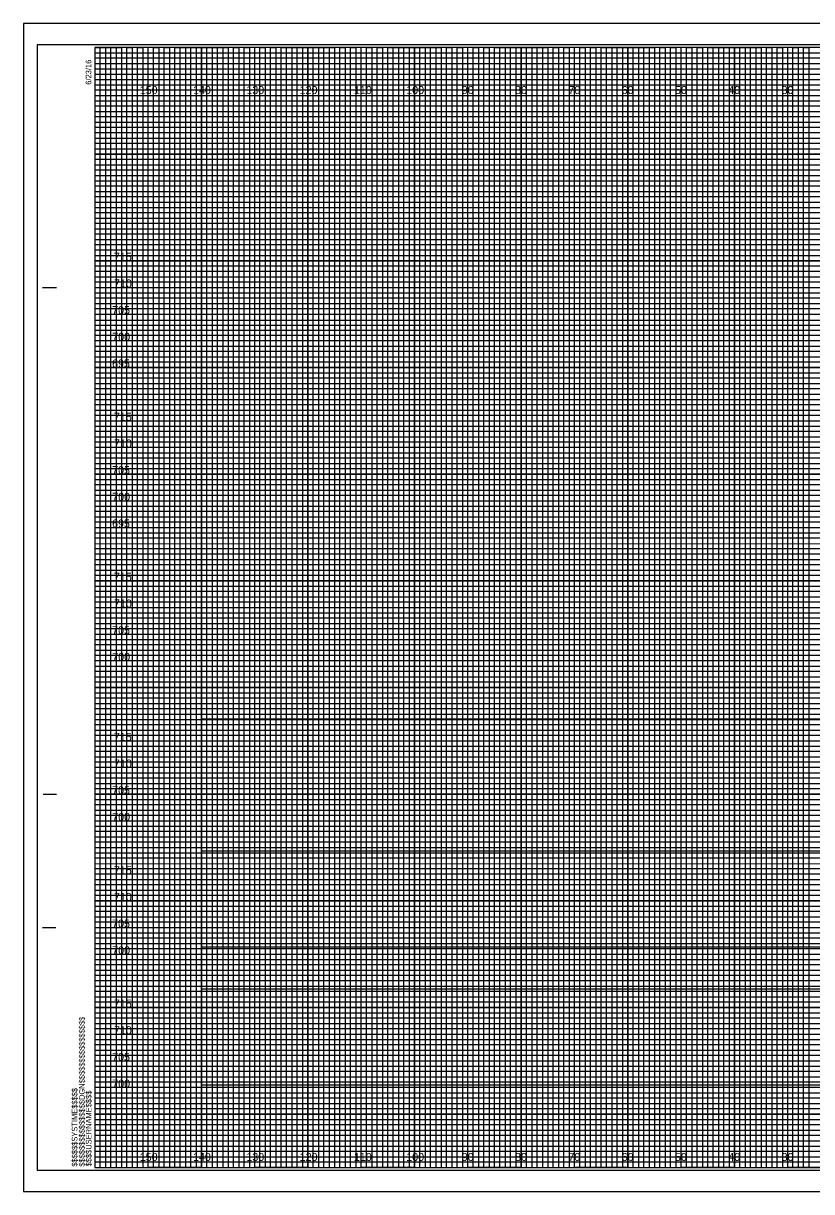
# Model space of a CAD drawing. Extents: x -13 to 323, y -5 to 215.
# Drawn here: x -13.4 to 134.5, y -4.5 to 214.5 of the extents above; entities that cross this region are included whole.
import ezdxf

# ---------------------------------------------------------------- set-up
doc = ezdxf.new("R2010")
doc.units = 0
for name, color, linetype in [('Prop XS Elevation Labels', 7, 'Continuous'), ('Prop XS Offset Labels', 7, 'Continuous'), ('Scratch_Level_3', 7, 'Continuous'), ('Sheet Cross Section CELL', 7, 'Continuous'), ('Sheet Cross Section Grid Major CELL', 7, 'Continuous'), ('Sheet Cross Section Grid Middle CELL', 7, 'Continuous'), ('Sheet Cross Section Grid Minor 1 CELL', 7, 'Continuous'), ('Sheet Cross Section Grid Minor 2 CELL', 7, 'Continuous'), ('Sheet Cutting Line CELL', 7, 'Continuous'), ('Sheet DOT Grid CELL', 7, 'Continuous'), ('Sheet Plot Border Inside CELL', 7, 'Continuous'), ('Sheet Plot Border Outside CELL', 7, 'Continuous')]:
    doc.layers.add(name, color=color, linetype=linetype)

msp = doc.modelspace()

# ---------------------------------------------------------------- linework, layer by layer
at = {"layer": 'Scratch_Level_3'}
for points in [[(20, 84.12), (300, 84.12), (300, 66.04), (20, 66.04)], [(20, 59.39), (300, 59.39), (300, 41.31), (20, 41.31)], [(20, 33.54), (300, 33.54), (300, 15.46), (20, 15.46)]]:
    msp.add_lwpolyline(points, close=True, dxfattribs=at)
at = {"layer": 'Sheet Cross Section CELL'}
for p, q in [((-9.8, 165), (-7.3, 165)), ((-9.7, 165), (-7.2, 165)), ((-9.7, 70), (-7.2, 70)), ((-9.8, 45), (-7.3, 45)), ((0, 0), (0, 0)), ((0, 0), (0, 0)), ((0, 0), (0, 0)), ((0, 0), (0, 0)), ((0, 0), (0, 0)), ((0, 0), (0, 0)), ((0, 0), (0, 0))]:
    msp.add_line(p, q, dxfattribs=at)
msp.add_lwpolyline([(320, 210), (0, 210), (0, 0), (320, 0)], close=True, dxfattribs=at)
at = {"layer": 'Sheet Cross Section Grid Major CELL'}
for p, q in [((10, 210), (0, 210)), ((10, 0), (10, 210)), ((30, 210), (20, 210)), ((20, 210), (20, 0)), ((30, 0), (30, 210)), ((50, 210), (40, 210)), ((40, 210), (40, 0)), ((50, 0), (50, 210)), ((70, 210), (60, 210)), ((60, 210), (60, 0)), ((70, 0), (70, 210)), ((90, 210), (80, 210)), ((80, 210), (80, 0)), ((90, 0), (90, 210)), ((110, 210), (100, 210)), ((100, 210), (100, 0)), ((110, 0), (110, 210)), ((130, 210), (120, 210)), ((120, 210), (120, 0)), ((130, 0), (130, 210)), ((20, 0), (10, 0)), ((40, 0), (30, 0)), ((60, 0), (50, 0)), ((80, 0), (70, 0)), ((100, 0), (90, 0)), ((120, 0), (110, 0)), ((140, 0), (130, 0))]:
    msp.add_line(p, q, dxfattribs=at)
for points in [[(0, 200), (320, 200), (320, 190), (0, 190)], [(0, 180), (320, 180), (320, 170), (0, 170)], [(0, 160), (320, 160), (320, 150), (0, 150)], [(0, 140), (320, 140), (320, 130), (0, 130)], [(0, 120), (320, 120), (320, 110), (0, 110)], [(0, 100), (320, 100), (320, 90), (0, 90)], [(0, 80), (320, 80), (320, 70), (0, 70)], [(0, 60), (320, 60), (320, 50), (0, 50)], [(0, 40), (320, 40), (320, 30), (0, 30)], [(0, 20), (320, 20), (320, 10), (0, 10)]]:
    msp.add_lwpolyline(points, dxfattribs=at)
at = {"layer": 'Sheet Cross Section Grid Middle CELL'}
for points in [[(0, 210), (5, 210), (5, 0), (15, 0), (15, 210), (25, 210), (25, 0), (35, 0), (35, 210), (45, 210), (45, 0), (55, 0), (55, 210), (65, 210), (65, 0), (75, 0), (75, 210), (85, 210), (85, 0), (95, 0), (95, 210), (105, 210), (105, 0), (115, 0), (115, 210), (125, 210), (125, 0), (135, 0)], [(0, 205), (275, 205)], [(0, 185), (320, 185), (320, 195), (0, 195)], [(0, 165), (320, 165), (320, 175), (0, 175)], [(0, 145), (320, 145), (320, 155), (0, 155)], [(0, 125), (320, 125), (320, 135), (0, 135)], [(0, 105), (320, 105), (320, 115), (0, 115)], [(0, 85), (320, 85), (320, 95), (0, 95)], [(0, 65), (320, 65), (320, 75), (0, 75)], [(0, 45), (320, 45), (320, 55), (0, 55)], [(0, 25), (320, 25), (320, 35), (0, 35)], [(0, 5), (320, 5), (320, 15), (0, 15)]]:
    msp.add_lwpolyline(points, dxfattribs=at)
at = {"layer": 'Sheet Cross Section Grid Minor 1 CELL'}
for p, q in [((0, 209), (260, 209)), ((260, 207.98), (0, 207.98)), ((0, 207.98), (0, 207)), ((0, 207), (260, 207)), ((260, 205.89), (0, 205.89)), ((0, 205.89), (0, 204)), ((0, 204), (320, 204))]:
    msp.add_line(p, q, dxfattribs=at)
for points in [[(0, 203), (270, 203), (320, 203), (320, 202), (0, 202)], [(0, 201), (320, 201), (320, 199), (0, 199)], [(0, 198), (320, 198), (320, 197), (0, 196.98)], [(0, 196), (320, 196), (320, 194), (0, 194)], [(0, 193), (320, 193), (320, 192), (0, 192)], [(0, 191), (320, 191), (320, 189), (0, 189)], [(0, 188), (320, 188), (320, 187), (0, 187)], [(0, 186), (320, 186), (320, 184), (0, 184)], [(0, 183), (320, 183), (320, 182), (0, 182)], [(0, 181), (320, 181), (320, 179), (0, 179)], [(0, 178), (320, 178), (320, 177), (0, 177)], [(0, 176), (320, 176), (320, 173.95), (320, 173), (320, 172), (0, 172)], [(0, 174), (320, 174), (320, 173), (0, 173)], [(0, 171), (320, 171), (320, 169), (0, 169.03)], [(0, 169.03), (320, 169), (320, 168), (0, 168)], [(0, 167), (320, 167), (320, 166), (0, 166)], [(0, 164), (320, 164), (320, 163), (0, 163)], [(0, 162), (320, 162), (320, 161), (0, 161)], [(-0.07, 158.89), (320, 158.89), (320, 157.88), (-0.07, 157.88)], [(0, 157), (320, 157), (320, 156), (0, 156)], [(0, 154), (320, 154), (320, 153), (0, 153)], [(0, 152), (320, 152), (320, 151), (0, 151)], [(0, 149), (320, 149), (320, 148), (0, 148)], [(0, 147), (320, 147), (320, 146), (0, 146)], [(0, 144), (320, 144), (320, 143), (0, 143)], [(0, 142), (320, 142), (320, 141), (0, 141)], [(0, 139), (320, 139), (319.99, 137.98), (0, 138)], [(0, 137), (320, 137), (320, 136), (0, 136)], [(0, 134), (320, 134), (320, 133), (0, 133)], [(0, 132), (320, 132), (320, 131), (0, 131)], [(0, 129), (320, 129), (320, 128), (0, 128)], [(0, 127), (320, 127), (320, 126), (0, 126)], [(0, 124), (320, 124), (320, 123), (0, 123)], [(0, 122), (320, 122), (320, 121), (0, 121)], [(0, 119), (320, 119), (320, 118), (0, 118)], [(0, 116.99), (320.07, 116.91), (320, 116), (0, 116)], [(0, 114), (320, 114), (320, 113), (0, 113)], [(0, 112), (320, 112), (320, 111), (0, 111)], [(0, 109), (320, 109), (320, 108), (0, 108)], [(0, 107), (320, 107), (320, 106), (0, 106)], [(0, 104), (320, 104), (320, 103), (0, 103)], [(0, 102), (320, 102), (320, 101), (0, 101)], [(0, 99), (320, 99), (320, 98), (0, 98)], [(0, 97), (320, 97), (320, 96), (0, 96)], [(0, 94), (320, 94), (320, 93), (0, 93)], [(0, 92), (320, 92), (320, 91), (0, 91)], [(0, 89), (320, 89), (320, 88), (0, 88)], [(0, 87), (320, 87), (320, 86), (0, 86)], [(0, 84), (320, 84), (320, 83), (0, 83)], [(0, 82), (320, 82), (320, 81), (0, 81)], [(0, 79), (320, 79), (319.99, 77.98), (0, 78)], [(0, 77), (320, 77), (320, 76), (0, 76)], [(0, 74), (320, 74), (320, 73), (0, 73)], [(0, 72), (320, 72), (320, 71), (0, 71)], [(0, 69), (320, 69), (320, 68), (0, 68)], [(0, 67), (320, 67), (320, 66), (0, 66)], [(0, 64), (320, 64), (320, 63), (0, 63)], [(0, 62), (320, 62), (320, 61), (0, 61)], [(0, 59), (320, 59), (320, 58), (0, 58)], [(0, 56.99), (320.07, 56.91), (320, 56), (0, 56)], [(0, 54), (320, 54), (320, 53), (0, 53)], [(0, 52), (320, 52), (320, 51), (0, 51)], [(0, 49), (320, 49), (320, 48), (0, 48)], [(0, 47), (320, 47), (320, 46), (0, 46)], [(0, 44), (320, 44), (320, 43), (0, 43)], [(0, 42), (320, 42), (320, 41), (0, 41)], [(0, 39), (320, 39), (320, 38), (0, 38)], [(0, 37), (320, 37), (320, 36), (0, 36)], [(0, 34), (320, 34), (320, 33), (0, 33)], [(0, 32), (320, 32), (320, 31), (0, 31)], [(0, 29), (320, 29), (320, 28), (0, 28)], [(0, 27), (320, 27), (320, 26), (0, 26)], [(0, 24), (320, 24), (320, 23), (0, 23)], [(0, 22), (320, 22), (320, 21), (0, 21)], [(0, 19), (320, 19), (320, 18), (0, 18)], [(0, 17), (320, 17), (320, 16), (0, 16)], [(0, 14), (320, 14), (320, 13), (0, 13)], [(0, 12), (320, 12), (320, 11), (0, 11)], [(0, 9), (320, 9), (320, 8), (0, 8)], [(0, 7), (320, 7), (320, 6), (0, 6)], [(0, 4), (320, 4), (320, 3), (0, 3)], [(0, 2), (320, 2), (320, 1), (0, 1)]]:
    msp.add_lwpolyline(points, dxfattribs=at)
at = {"layer": 'Sheet Cross Section Grid Minor 2 CELL'}
for points in [[(0, 0), (1, 0), (1, 210), (2, 210), (2, 0)], [(2, 0), (3, 0), (3, 210), (4, 210), (4, 0)], [(5, 0), (6, 0), (6, 210), (7, 210), (7, 0)], [(7, 0), (8, 0), (8, 210), (9, 210), (9, 0)], [(10, 0), (11, 0), (11, 210), (12, 210), (12, 0)], [(12, 0), (13, 0), (13, 210), (14, 210), (14, 0)], [(15, 0), (16, 0), (16, 210), (17, 210), (17, 0)], [(17, 0), (18, 0), (18, 210), (19, 210), (19, 0)], [(20, 0), (21, 0), (21, 210), (22, 210), (22, 0)], [(22, 0), (23, 0), (23, 210), (24, 210), (24, 0)], [(25, 0), (26, 0), (26, 210), (27, 210), (27, 0)], [(27, 0), (28, 0), (28, 210), (29, 210), (29, 0)], [(30, 0), (31, 0), (31, 210), (32, 210), (32, 0)], [(32, 0), (33, 0), (33, 210), (34, 210), (34, 0)], [(35, 0), (36, 0), (36, 210), (37, 210), (37, 0)], [(37, 0), (38, 0), (38, 210), (39, 210), (39, 0)], [(40, 0), (41, 0), (41, 210), (42, 210), (42, 0)], [(42, 0), (43, 0), (43, 210), (44, 210), (44, 0)], [(45, 0), (46, 0), (46, 210), (47, 210), (47, 0)], [(47, 0), (48, 0), (48, 210), (49, 210), (49, 0)], [(50, 0), (51, 0), (51, 210), (52, 210), (52, 0)], [(52, 0), (53, 0), (53, 210), (54, 210), (54, 0)], [(55, 0), (56, 0), (56, 210), (57, 210), (57, 0)], [(57, 0), (58, 0), (58, 210), (59, 210), (59, 0)], [(60, 0), (61, 0), (61, 210), (62, 210), (62, 0)], [(62, 0), (63, 0), (63, 210), (64, 210), (64, 0)], [(65, 0), (66, 0), (66, 210), (67, 210), (67, 0)], [(67, 0), (68, 0), (68, 210), (69, 210), (69, 0)], [(70, 0), (71, 0), (71, 210), (72, 210), (72, 0)], [(72, 0), (73, 0), (73, 210), (74, 210), (74, 0)], [(75, 0), (76, 0), (76, 210), (77, 210), (77, 0)], [(77, 0), (78, 0), (78, 210), (79, 210), (79, 0)], [(80, 0), (81, 0), (81, 210), (82, 210), (82, 0)], [(82, 0), (83, 0), (83, 210), (84, 210), (84, 0)], [(85, 0), (86, 0), (86, 210), (87, 210), (87, 0)], [(87, 0), (88, 0), (88, 210), (89, 210), (89, 0)], [(90, 0), (91, 0), (91, 210), (92, 210), (92, 0)], [(92, 0), (93, 0), (93, 210), (94, 210), (94, 0)], [(95, 0), (96, 0), (96, 210), (97, 210), (97, 0)], [(97, 0), (98, 0), (98, 210), (99, 210), (99, 0)], [(100, 0), (101, 0), (101, 210), (102, 210), (102, 0)], [(102, 0), (103, 0), (103, 210), (104, 210), (104, 0)], [(105, 0), (106, 0), (106, 210), (107, 210), (107, 0)], [(107, 0), (108, 0), (108, 210), (109, 210), (109, 0)], [(110, 0), (111, 0), (111, 210), (112, 210), (112, 0)], [(112, 0), (113, 0), (113, 210), (114, 210), (114, 0)], [(115, 0), (116, 0), (116, 210), (117, 210), (117, 0)], [(117, 0), (118, 0), (118, 210), (119, 210), (119, 0)], [(120, 0), (121, 0), (121, 210), (122, 210), (122, 0)], [(122, 0), (123, 0), (123, 210), (124, 210), (124, 0)], [(125, 0), (126, 0), (126, 210), (127, 210), (127, 0)], [(127, 0), (128, 0), (128, 210), (129, 210), (129, 0)], [(130, 0), (131, 0), (131, 210), (132, 210), (132, 0)], [(132, 0), (133, 0), (133, 210), (134, 210), (134, 0)]]:
    msp.add_lwpolyline(points, dxfattribs=at)
at = {"layer": 'Sheet Cutting Line CELL'}
for p, q in [((323.3, 214.5), (-13.4, 214.5)), ((-13.4, 214.5), (-13.4, -4.5)), ((-13.4, -4.5), (323.3, -4.5))]:
    msp.add_line(p, q, dxfattribs=at)
at = {"layer": 'Sheet DOT Grid CELL'}
for p, q in [((10, 0), (10, 210)), ((20, 0), (20, 210)), ((30, 0), (30, 210)), ((40, 0), (40, 210)), ((50, 0), (50, 210)), ((60, 0), (60, 210)), ((70, 0), (70, 210)), ((80, 0), (80, 210)), ((90, 0), (90, 210)), ((100, 0), (100, 210)), ((110, 0), (110, 210)), ((120, 0), (120, 210)), ((130, 0), (130, 210)), ((0, 200), (320, 200)), ((0, 190), (320, 190)), ((0, 180), (320, 180)), ((0, 170), (320, 170)), ((0, 160), (320, 160)), ((0, 150), (320, 150)), ((0, 140), (320, 140)), ((0, 130), (320, 130)), ((0, 120), (320, 120)), ((0, 110), (320, 110)), ((0, 100), (320, 100)), ((0, 90), (320, 90)), ((0, 80), (320, 80)), ((0, 70), (320, 70)), ((0, 60), (320, 60)), ((0, 50), (320, 50)), ((0, 40), (320, 40)), ((0, 30), (320, 30)), ((0, 20), (320, 20)), ((0, 10), (320, 10))]:
    msp.add_line(p, q, dxfattribs=at)
at = {"layer": 'Sheet Plot Border Inside CELL'}
msp.add_lwpolyline([(-10.8, -0.5), (322.4, -0.5), (322.4, 210.5), (-10.8, 210.5)], close=True, dxfattribs=at)
at = {"layer": 'Sheet Plot Border Outside CELL'}
msp.add_lwpolyline([(-13.4, -4.5), (323.3, -4.5), (323.3, 214.5), (-13.4, 214.5)], close=True, dxfattribs=at)

# ---------------------------------------------------------------- texts
at = {"layer": 'Prop XS Elevation Labels'}
for s, p in [('715', (3.59, 170)), ('710', (3.61, 165)), ('705', (3.26, 160)), ('700', (3.28, 155)), ('695', (3.25, 150)), ('715', (3.59, 140)), ('710', (3.61, 135)), ('705', (3.26, 130)), ('700', (3.28, 125)), ('695', (3.25, 120)), ('715', (3.59, 110)), ('710', (3.61, 105)), ('705', (3.26, 100)), ('700', (3.28, 95)), ('715', (3.59, 80)), ('710', (3.61, 75)), ('705', (3.26, 70)), ('700', (3.28, 65)), ('715', (3.59, 55)), ('710', (3.61, 50)), ('705', (3.26, 45)), ('700', (3.28, 40)), ('715', (3.59, 30)), ('710', (3.61, 25)), ('705', (3.26, 20)), ('700', (3.28, 15))]:
    msp.add_text(s, height=1.5, dxfattribs=at).set_placement(p)
at = {"layer": 'Prop XS Offset Labels'}
for s, p in [('150', (8.44, 201.25)), ('140', (18.44, 201.25)), ('130', (28.44, 201.25)), ('120', (38.44, 201.25)), ('110', (48.62, 201.25)), ('100', (58.44, 201.25)), ('90', (68.86, 201.25)), ('80', (78.86, 201.25)), ('70', (88.86, 201.25)), ('60', (98.86, 201.25)), ('50', (108.86, 201.25)), ('40', (118.86, 201.25)), ('30', (128.86, 201.25)), ('150', (8.44, 1.25)), ('140', (18.44, 1.25)), ('130', (28.44, 1.25)), ('120', (38.44, 1.25)), ('110', (48.62, 1.25)), ('100', (58.44, 1.25)), ('90', (68.86, 1.25)), ('80', (78.86, 1.25)), ('70', (88.86, 1.25)), ('60', (98.86, 1.25)), ('50', (108.86, 1.25)), ('40', (118.86, 1.25)), ('30', (128.86, 1.25))]:
    msp.add_text(s, height=1.5, dxfattribs=at).set_placement(p)
at = {"layer": 'Sheet Cross Section CELL'}
for s, p in [('6/23/16', (-0.65, 203)), ('$$$$$$$$$$$$$$$$DGN$$$$$$$$$$$$$$$$', (-1.88, 0.18)), ('$$$$$$SYSTIME$$$$$', (-3.26, 0.18)), ('$$$$USERNAME$$$$', (-0.62, 0.23))]:
    msp.add_text(s, height=1.05, rotation=90, dxfattribs=at).set_placement(p)

doc.saveas('drawing.dxf')
